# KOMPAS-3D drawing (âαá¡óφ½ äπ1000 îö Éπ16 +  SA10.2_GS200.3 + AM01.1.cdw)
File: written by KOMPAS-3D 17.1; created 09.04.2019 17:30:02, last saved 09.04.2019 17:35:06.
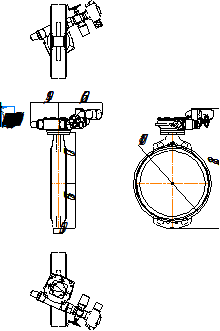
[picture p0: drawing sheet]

Sheet 1: A4, portrait

Title block, sheet 1: name: Гранвэл Ду1000 МФ Ру16 + / SA10.2_GS200.3 + AM01.1; material: Внимание! Данный продукт является объектом авторского права ООО «Торговый Дом АДЛ». / Запрещается изменение, копирование, распространение / (в том числе путем копирования на другие сайты и ресурсы в Интернете) / или любое иное использование информации и объектов без предварительного / согласия правообладателя (ООО «Торговый Дом АДЛ»).; mass: 1368,51; sheets: 1; organisation: ООО "Торговый дом АДЛ"; sheet format: A4

Views: Вид 1, Спереди, Проекционный вид 2, Проекционный вид 3
Referenced files in \\adlc.lan\data\АДЛ_ПКД\3D-модели\ADL production\Дисковые поворотные затворы ГРАНВЭЛ\межфланцевый с эл.приводом Auma Ру 16\KOMPAS 3D\: Гранвэл Ду1000 МФ Ру16 + SA10.2_GS200.3 + AM01.1.m3d
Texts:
  user
Dimensions and other numbers on the sheet: 770; 675; 150; 419,19; 660,52; 1:1; 1; 1368,51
